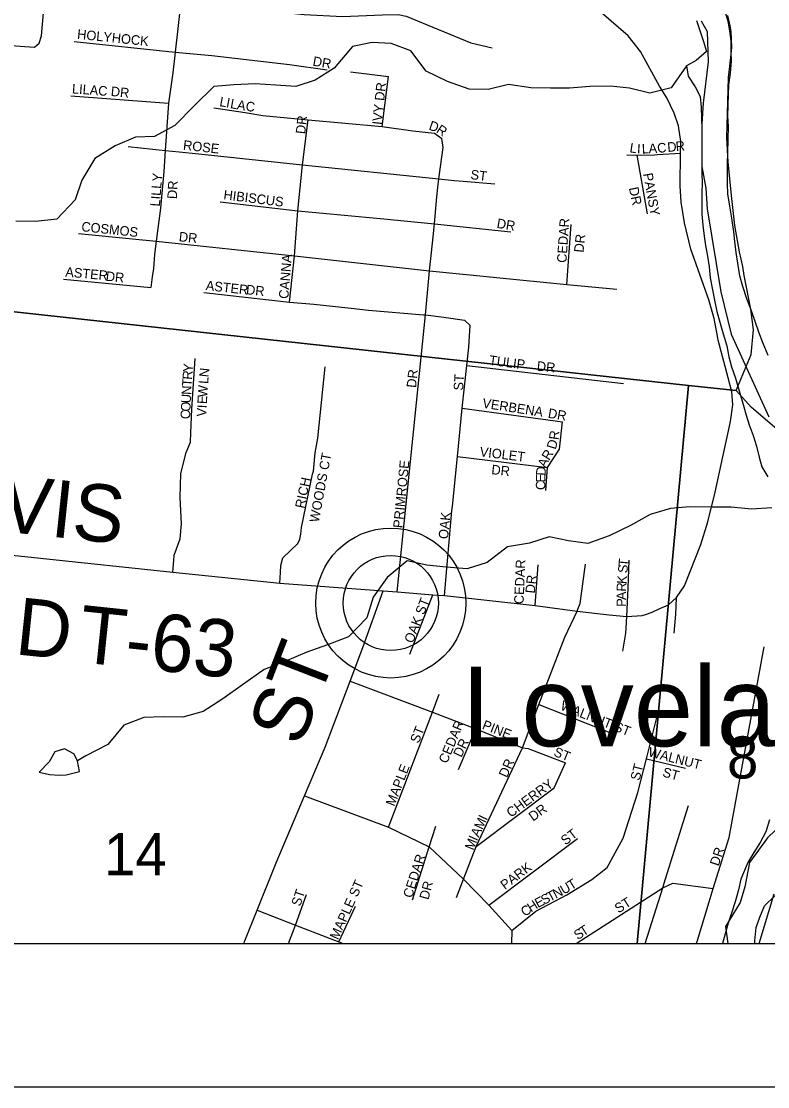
# Model space of a CAD drawing. Extents: x 0 to 34, y -4 to 22.
# Drawn here: x 3.386 to 3.907, y 14 to 14.744 of the extents above; entities that cross this region are included whole.
import ezdxf

# ---------------------------------------------------------------- set-up
doc = ezdxf.new("R2010")
doc.units = 0
for name, color, linetype in [('GM_X_Major_River', 7, 'Continuous'), ('GM_X_Minor_Lake', 7, 'Continuous'), ('GM_X_Minor_River', 7, 'Continuous'), ('GM_X_Section', 7, 'Continuous'), ('GM_X_Section_Text', 7, 'Continuous'), ('GM_X_Township', 7, 'Continuous'), ('GM_X_Township_Road', 7, 'Continuous'), ('GM_X_Township_Road_Text', 7, 'Continuous'), ('GM_X_Township_Subdivision', 7, 'Continuous'), ('GM_X_Township_Subdivision_Text', 7, 'Continuous'), ('GM_X_Unincorporated', 7, 'Continuous'), ('GM_X_Unincorporated_Text', 7, 'Continuous'), ('SH_Data', 7, 'Continuous'), ('SN_P_Text', 7, 'Continuous')]:
    doc.layers.add(name, color=color, linetype=linetype)

msp = doc.modelspace()

# ---------------------------------------------------------------- linework, layer by layer
at = {"layer": 'GM_X_Major_River'}
for points in [[(3.9041, 14.51904), (3.90103, 14.52686), (3.89874, 14.5336), (3.89594, 14.54169), (3.89261, 14.55005), (3.88982, 14.55868), (3.88782, 14.56621), (3.88637, 14.57508), (3.88516, 14.5826), (3.88423, 14.59012), (3.88354, 14.59683), (3.88211, 14.6065), (3.88065, 14.61483), (3.87947, 14.62342), (3.87906, 14.63039), (3.87918, 14.63735), (3.87905, 14.64486), (3.87944, 14.65181), (3.87962, 14.66172), (3.87978, 14.67055), (3.87937, 14.67779), (3.8795, 14.68529), (3.8799, 14.69278), (3.88002, 14.69948), (3.88124, 14.70776), (3.88192, 14.71605), (3.88178, 14.72274), (3.88164, 14.73025), (3.8807, 14.73723), (3.87948, 14.74395), (3.8772, 14.75122)], [(3.85754, 14.74463), (3.86008, 14.73681), (3.86236, 14.7298), (3.86438, 14.7228), (3.85731, 14.71651), (3.85055, 14.71289), (3.85176, 14.70563), (3.85645, 14.69831), (3.86008, 14.69155), (3.86074, 14.68403), (3.86087, 14.676), (3.86127, 14.66876)], [(3.86127, 14.66876), (3.8611, 14.65912), (3.86125, 14.65242), (3.86113, 14.64546), (3.86126, 14.63796), (3.86141, 14.63099), (3.86129, 14.6243), (3.86117, 14.6176), (3.86129, 14.6093), (3.86195, 14.60152), (3.86289, 14.594), (3.86384, 14.58729), (3.86505, 14.58003), (3.86625, 14.57251), (3.86691, 14.56473), (3.86864, 14.5564), (3.87011, 14.54914), (3.87158, 14.54134), (3.87385, 14.5338), (3.87612, 14.52572), (3.87864, 14.51737), (3.88011, 14.50958), (3.88186, 14.50258), (3.88466, 14.49476), (3.88769, 14.48426), (3.88996, 14.47645), (3.89223, 14.4689), (3.89425, 14.46217), (3.89706, 14.45462), (3.89934, 14.44734), (3.90134, 14.43954), (3.90309, 14.43281), (3.90725, 14.42577)], [(3.90743, 14.51067), (3.9041, 14.51904)], [(3.90856, 14.1863), (3.906, 14.17805), (3.90185, 14.17062), (3.89744, 14.16348), (3.8933, 14.15659), (3.88854, 14.14489), (3.8868, 14.13743), (3.88451, 14.12917), (3.88196, 14.12118), (3.87969, 14.11426), (3.87742, 14.1068), (3.87559, 14.1)], [(3.89817, 14.1), (3.8982, 14.10186), (3.89917, 14.11122), (3.90171, 14.1184), (3.90507, 14.12637), (3.91215, 14.1332)]]:
    msp.add_lwpolyline(points, dxfattribs=at)
at = {"layer": 'GM_X_Minor_Lake'}
for points in [[(3.42524, 14.22764), (3.42284, 14.23244), (3.41615, 14.23592), (3.40947, 14.23378), (3.40546, 14.22683), (3.39851, 14.21962), (3.40573, 14.21802), (3.41241, 14.21748), (3.41732, 14.21787)], [(3.41732, 14.21787), (3.42658, 14.22015), (3.42524, 14.22764)]]:
    msp.add_lwpolyline(points, dxfattribs=at)
at = {"layer": 'GM_X_Minor_River'}
for points in [[(3.85055, 14.71289), (3.8397, 14.69743), (3.82499, 14.69369), (3.81081, 14.69717), (3.79743, 14.69877), (3.78299, 14.6985), (3.76881, 14.69717), (3.75543, 14.69717), (3.74179, 14.69744), (3.72627, 14.69984), (3.71209, 14.69637), (3.69872, 14.69663), (3.68373, 14.70198), (3.66875, 14.7092), (3.65805, 14.72336), (3.6444, 14.72844), (3.63102, 14.72925), (3.61738, 14.72631), (3.60454, 14.71134), (3.59117, 14.70278), (3.57779, 14.69851), (3.56388, 14.69931), (3.54944, 14.70038), (3.53446, 14.69958), (3.52055, 14.69851), (3.50691, 14.68514), (3.49327, 14.67124), (3.47909, 14.66349), (3.46571, 14.66296), (3.45153, 14.65708), (3.43736, 14.64826), (3.42827, 14.63302), (3.42372, 14.61939), (3.41088, 14.60576), (3.3959, 14.60415), (3.38226, 14.60442)], [(3.91012, 14.4042), (3.89594, 14.4034), (3.88176, 14.40474), (3.86839, 14.40474), (3.85314, 14.405), (3.83923, 14.40367), (3.82505, 14.39966), (3.81141, 14.39191), (3.79643, 14.38469), (3.78171, 14.37934), (3.76807, 14.38122), (3.75469, 14.38389), (3.74078, 14.37961), (3.72553, 14.37694), (3.71136, 14.36598), (3.69744, 14.3617), (3.68273, 14.36277), (3.66909, 14.36411), (3.65544, 14.36732), (3.64153, 14.35556), (3.63164, 14.34193), (3.62736, 14.32749), (3.61452, 14.31413), (3.5998, 14.30851), (3.58536, 14.30344), (3.57011, 14.29702), (3.55566, 14.29141), (3.54042, 14.28072), (3.52677, 14.27083), (3.51313, 14.26201), (3.49895, 14.258), (3.48531, 14.25827), (3.47166, 14.25773), (3.45775, 14.25239), (3.44652, 14.23902), (3.431, 14.231), (3.42524, 14.22764)]]:
    msp.add_lwpolyline(points, dxfattribs=at)
at = {"layer": 'GM_X_Section'}
for points in [[(3.15948, 14.56518), (3.85199, 14.48967), (3.88525, 14.48607), (3.89561, 14.51119), (3.8973, 14.52848), (3.89545, 14.54292), (3.89086, 14.56648), (3.88992, 14.57263), (3.88746, 14.58307), (3.88436, 14.60127), (3.88208, 14.62024), (3.87966, 14.64562), (3.87866, 14.66271), (3.87978, 14.70481), (3.88139, 14.71865), (3.88207, 14.72583), (3.88176, 14.73677), (3.88104, 14.74078), (3.87931, 14.74802)], [(3.92005, 14.45363), (3.89594, 14.47439), (3.88525, 14.48607), (3.85199, 14.48967), (3.81604, 14.1), (3.90131, 14.1), (3.91178, 14.13465)]]:
    msp.add_lwpolyline(points, dxfattribs=at)
msp.add_lwpolyline([(3.10877, 14.1), (3.81604, 14.1), (3.85199, 14.48967), (3.15948, 14.56518)], close=True, dxfattribs=at)
at = {"layer": 'GM_X_Township'}
for points in [[(3.86069, 14.74433), (3.86489, 14.73695), (3.86564, 14.71564), (3.86222, 14.68684), (3.86111, 14.67268), (3.86114, 14.64255), (3.86389, 14.62743), (3.86495, 14.61294), (3.87457, 14.55512), (3.88172, 14.52545), (3.90792, 14.4677)], [(3.92411, 14.19005), (3.907, 14.17387), (3.89445, 14.15645), (3.89131, 14.1395), (3.88789, 14.12859), (3.8777, 14.11185), (3.87935, 14.1), (7.6703, 14.1)]]:
    msp.add_lwpolyline(points, dxfattribs=at)
at = {"layer": 'GM_X_Township_Road'}
for points in [[(3.87164, 14.52664), (3.86979, 14.53639), (3.8661, 14.54953), (3.85359, 14.58481), (3.84918, 14.60317), (3.84684, 14.61758), (3.84606, 14.62901), (3.84639, 14.6519), (3.84652, 14.66012), (3.84491, 14.67092), (3.84179, 14.67987), (3.83687, 14.69057), (3.83162, 14.6987), (3.81849, 14.72297), (3.80985, 14.73377), (3.78599, 14.75437)], [(3.87657, 14.44302), (3.87861, 14.45268), (3.88131, 14.46448), (3.88275, 14.47618), (3.88212, 14.48527), (3.87969, 14.4949), (3.87267, 14.52118), (3.87164, 14.52664)], [(3.82195, 14.32981), (3.82659, 14.33145), (3.83181, 14.33388), (3.83793, 14.33658), (3.8436, 14.34153), (3.84909, 14.34981), (3.86052, 14.37852), (3.86547, 14.39436), (3.87042, 14.41516), (3.87591, 14.43991), (3.87657, 14.44302)], [(3.30692, 14.37873), (3.49185, 14.35933), (3.56652, 14.35168), (3.63865, 14.34636), (3.6486, 14.34545), (3.67341, 14.34338), (3.68142, 14.343), (3.74478, 14.33595), (3.77415, 14.33212), (3.79644, 14.32947), (3.80877, 14.32839), (3.81948, 14.32893), (3.82195, 14.32981)], [(3.54144, 14.1), (3.54211, 14.1018), (3.5507, 14.12317), (3.56399, 14.15625), (3.58383, 14.20303), (3.59826, 14.23707), (3.61564, 14.28317), (3.62447, 14.30657), (3.63865, 14.34636)]]:
    msp.add_lwpolyline(points, dxfattribs=at)
at = {"layer": 'GM_X_Township_Subdivision'}
for points in [[(3.50538, 14.82838), (3.50071, 14.79605), (3.4987, 14.77523), (3.49739, 14.75759), (3.49345, 14.72231), (3.49192, 14.70786), (3.48874, 14.68683), (3.48646, 14.65384), (3.48549, 14.63897), (3.48331, 14.61342), (3.48031, 14.59038), (3.47958, 14.58508)], [(3.3952, 14.72586), (3.39849, 14.72871), (3.40013, 14.73379), (3.40163, 14.74987), (3.40335, 14.76873), (3.4042, 14.77779), (3.40519, 14.78066), (3.40663, 14.78614), (3.40674, 14.79186), (3.40534, 14.79432), (3.40251, 14.79513), (3.39944, 14.7945), (3.39785, 14.79292), (3.39722, 14.79027), (3.39817, 14.78752), (3.40029, 14.78582), (3.40229, 14.7835), (3.40431, 14.78117)], [(3.42469, 14.76541), (3.49739, 14.75759), (3.58357, 14.74866), (3.61027, 14.74728), (3.63835, 14.74839), (3.64928, 14.74866), (3.65481, 14.74756), (3.69991, 14.72888), (3.71471, 14.72543)], [(3.18884, 14.68116), (3.20908, 14.6793), (3.22743, 14.67658), (3.23539, 14.67574), (3.24391, 14.6763), (3.25324, 14.67805), (3.26511, 14.68283), (3.27157, 14.68674), (3.28623, 14.6971), (3.30592, 14.71168), (3.31696, 14.71943), (3.325, 14.72533), (3.33507, 14.72918), (3.34215, 14.73036), (3.35051, 14.7294), (3.35963, 14.72863), (3.37205, 14.72747), (3.3952, 14.72586)], [(3.42289, 14.72985), (3.49345, 14.72231), (3.51904, 14.72017), (3.57327, 14.71387), (3.59955, 14.71014)], [(3.6159, 14.70871), (3.64248, 14.7055)], [(3.63798, 14.67055), (3.64248, 14.7055)], [(3.42068, 14.69181), (3.48874, 14.68683)], [(3.5204, 14.68352), (3.54233, 14.68017)], [(3.54233, 14.68017), (3.5548, 14.67827), (3.58642, 14.67527)], [(3.57321, 14.54787), (3.57677, 14.5803), (3.57907, 14.61168), (3.58246, 14.64365), (3.58642, 14.67527)], [(3.58642, 14.67527), (3.63798, 14.67055), (3.65931, 14.66755), (3.67463, 14.66573), (3.67956, 14.66219)], [(3.46073, 14.6566), (3.48646, 14.65384), (3.49627, 14.65283)], [(3.67686, 14.62789), (3.67753, 14.6339), (3.68053, 14.65576), (3.67956, 14.66219)], [(3.49627, 14.65283), (3.50998, 14.65142), (3.58246, 14.64365), (3.67753, 14.6339), (3.68827, 14.63288)], [(3.80887, 14.65077), (3.81611, 14.65042), (3.82823, 14.6508)], [(3.82316, 14.60953), (3.81611, 14.65042)], [(3.82823, 14.6508), (3.83028, 14.65087), (3.84639, 14.6519)], [(3.67362, 14.59343), (3.67463, 14.6026), (3.67613, 14.62146), (3.67686, 14.62789)], [(3.68827, 14.63288), (3.69457, 14.63229), (3.71676, 14.63047)], [(3.5249, 14.61793), (3.57907, 14.61168), (3.63926, 14.60603), (3.66991, 14.60306)], [(3.66991, 14.60306), (3.67463, 14.6026), (3.72791, 14.59702)], [(3.76692, 14.56015), (3.76992, 14.60217)], [(3.42596, 14.59585), (3.48031, 14.59038), (3.57677, 14.5803), (3.6711, 14.5698), (3.76692, 14.56015), (3.80187, 14.55694)], [(3.6486, 14.34545), (3.6683, 14.53888), (3.6711, 14.5698), (3.67313, 14.58909), (3.67362, 14.59343)], [(3.47958, 14.58508), (3.47902, 14.58105), (3.47827, 14.5713), (3.47752, 14.56562), (3.47656, 14.55801)], [(3.41556, 14.5638), (3.47656, 14.55801)], [(3.51349, 14.55453), (3.57321, 14.54787)], [(3.57321, 14.54787), (3.59031, 14.54642), (3.61641, 14.54365)], [(3.61641, 14.54365), (3.62858, 14.54236), (3.66683, 14.53901)], [(3.66683, 14.53901), (3.6683, 14.53888), (3.68105, 14.53743), (3.6955, 14.53516)], [(3.68706, 14.40542), (3.69072, 14.44005), (3.69383, 14.47391), (3.69706, 14.5035), (3.69848, 14.51642), (3.69951, 14.53154), (3.6955, 14.53516)], [(3.49185, 14.35933), (3.4925, 14.36748), (3.49289, 14.37119), (3.49691, 14.38251), (3.49788, 14.3931), (3.49691, 14.41139), (3.49753, 14.42809), (3.50124, 14.44294), (3.50413, 14.45009), (3.5044, 14.45655), (3.50523, 14.47305), (3.50619, 14.49092), (3.5075, 14.50859)], [(3.56652, 14.35168), (3.56703, 14.35915), (3.56736, 14.36405), (3.56871, 14.3692), (3.57921, 14.37938), (3.58056, 14.38234), (3.58127, 14.38582), (3.58178, 14.39046), (3.5894, 14.42777), (3.58999, 14.42993), (3.59113, 14.44259), (3.59307, 14.45295), (3.59824, 14.50276)], [(3.69706, 14.5035), (3.80657, 14.49112)], [(3.69383, 14.47391), (3.76391, 14.46432)], [(3.75237, 14.41627), (3.7534, 14.43242), (3.76173, 14.44518), (3.76391, 14.46432)], [(3.69072, 14.44005), (3.7534, 14.43242)], [(3.68142, 14.343), (3.68672, 14.40218), (3.68706, 14.40542)], [(3.80985, 14.34805), (3.80985, 14.3481), (3.81057, 14.36772)], [(3.74478, 14.33595), (3.74694, 14.3643)], [(3.77471, 14.33353), (3.77619, 14.3373), (3.78007, 14.36499)], [(3.80839, 14.32023), (3.80877, 14.32839), (3.80985, 14.34805)], [(3.65739, 14.30203), (3.67341, 14.34338)], [(3.84331, 14.33533), (3.8436, 14.34153)], [(3.6948, 14.14488), (3.70374, 14.16769), (3.73596, 14.23659), (3.74748, 14.26692), (3.76548, 14.31399), (3.77415, 14.33212), (3.77471, 14.33353)], [(3.842, 14.31678), (3.84306, 14.33001), (3.84331, 14.33533)], [(3.80607, 14.30409), (3.80823, 14.31669), (3.80839, 14.32023)], [(3.86626, 14.12899), (3.86631, 14.12915), (3.86918, 14.13837), (3.88027, 14.17394), (3.90468, 14.30711)], [(3.61564, 14.28317), (3.67304, 14.26143), (3.70348, 14.24991), (3.73596, 14.23659), (3.73993, 14.2361), (3.741, 14.2357)], [(3.64243, 14.18123), (3.67304, 14.26143), (3.6779, 14.27418)], [(3.74748, 14.26692), (3.79815, 14.24694)], [(3.72848, 14.10898), (3.7454, 14.12257), (3.76704, 14.13404), (3.78444, 14.14465), (3.79515, 14.15306), (3.80622, 14.17362), (3.81655, 14.20541), (3.82249, 14.22891), (3.82979, 14.25785)], [(3.69133, 14.22151), (3.70348, 14.24991)], [(3.741, 14.2357), (3.7661, 14.22619)], [(3.70374, 14.16769), (3.75812, 14.20858), (3.7661, 14.22619)], [(3.82249, 14.22891), (3.84969, 14.22252)], [(3.58383, 14.20303), (3.64243, 14.18123), (3.67089, 14.1674), (3.6948, 14.14488), (3.7124, 14.12672), (3.72848, 14.10898), (3.72822, 14.1)], [(3.83461, 14.14128), (3.83463, 14.14136), (3.85193, 14.19647)], [(3.65917, 14.13038), (3.67089, 14.1674), (3.6755, 14.18193)], [(3.7124, 14.12672), (3.77433, 14.17323)], [(3.68984, 14.1322), (3.6948, 14.14488)], [(3.77343, 14.1), (3.83387, 14.13894), (3.84095, 14.14212), (3.84103, 14.14211)], [(3.82165, 14.1), (3.83387, 14.13894), (3.83461, 14.14128)], [(3.84103, 14.14211), (3.86918, 14.13837)], [(3.57272, 14.1), (3.57739, 14.11286), (3.58513, 14.13412)], [(3.85732, 14.1), (3.85783, 14.10135), (3.86626, 14.12899)], [(3.5507, 14.12317), (3.57739, 14.11286), (3.60765, 14.10117), (3.61069, 14.1)], [(3.60765, 14.10117), (3.61928, 14.12605)]]:
    msp.add_lwpolyline(points, dxfattribs=at)
at = {"layer": 'GM_X_Unincorporated'}
for radius in [0.05238, 0.0332]:
    msp.add_circle((3.64404, 14.33775), radius, dxfattribs=at)
at = {"layer": 'SH_Data'}
for p, q in [((2.1, 14.1), (8.9, 14.1)), ((2, 14), (9, 14))]:
    msp.add_line(p, q, dxfattribs=at)
at = {"layer": 'SN_P_Text'}
msp.add_lwpolyline([(8.9, 14.1), (8.9, 20.9), (2.1, 20.9), (2.1, 14.1)], close=True, dxfattribs=at)

# ---------------------------------------------------------------- texts
at = {"layer": 'GM_X_Section_Text'}
for s, height, p in [('8', 0.02944, (3.87878, 14.21519)), ('14', 0.029444, (3.44377, 14.14765))]:
    msp.add_text(s, height=height, rotation=0.00001, dxfattribs=at).set_placement(p)
at = {"layer": 'GM_X_Township_Road_Text'}
for s, rotation, p in [('DAVIS', 353.93703, (3.29632, 14.39585)), ('RD', 354.04225, (3.34248, 14.30604)), ('T-63', 354.00977, (3.42485, 14.2966)), ('ST', 68.93202, (3.581, 14.23643))]:
    msp.add_text(s, height=0.04, rotation=rotation, dxfattribs=at).set_placement(p)
at = {"layer": 'GM_X_Township_Subdivision_Text'}
for s, height, rotation, p in [('HOLYHOCK', 0.006667, 354.14157, (3.42483, 14.73178)), ('DR', 0.006667, 350.53177, (3.58918, 14.71299)), ('IVY DR', 0.006667, 83.93096, (3.63759, 14.67141)), ('LILAC', 0.006667, 355.81741, (3.42127, 14.69365)), ('DR', 0.006667, 353.98321, (3.4483, 14.69188)), ('L', 0.00667, 349.42397, (3.52408, 14.68483)), ('I', 0.00667, 349.42924, (3.5287, 14.68397)), ('L', 0.00667, 349.41896, (3.53158, 14.68343)), ('A', 0.00667, 349.87549, (3.53625, 14.68256)), ('C', 0.00667, 353.24852, (3.54245, 14.68146)), ('DR', 0.006667, 83.66379, (3.58421, 14.66496)), ('D', 0.00667, 341.12969, (3.67009, 14.66843)), ('R', 0.00667, 326.35709, (3.67524, 14.66673)), ('ROSE', 0.006667, 353.65714, (3.49876, 14.65434)), ('L', 0.00667, 351.0856, (3.81046, 14.65255)), ('I', 0.00667, 356.57117, (3.81579, 14.65175)), ('L', 0.00667, 2.36536, (3.81945, 14.65156)), ('A', 0.00667, 2.90186, (3.82421, 14.65176)), ('C', 0.00667, 4.84004, (3.83031, 14.65207)), ('D', 0.00667, 5.36843, (3.8374, 14.65269)), ('R', 0.00667, 5.35054, (3.84324, 14.65323)), ('LILLY', 0.006667, 85.71328, (3.48279, 14.61446)), ('ST', 0.006667, 352.88003, (3.69942, 14.6338)), ('PANSY', 0.006667, 280.07945, (3.82018, 14.63747)), ('DR', 0.006667, 86.98901, (3.49462, 14.61971)), ('HIBISCUS', 0.006667, 352.76357, (3.52694, 14.61972)), ('DR', 0.006667, 281.89272, (3.81024, 14.62754)), ('COSMOS', 0.006667, 353.9904, (3.42777, 14.59743)), ('DR', 0.006667, 350.54359, (3.71766, 14.59977)), ('CEDAR', 0.006667, 86.26602, (3.76665, 14.57514)), ('DR', 0.006667, 353.99339, (3.49582, 14.59039)), ('DR', 0.006667, 83.9832, (3.77852, 14.58222)), ('CANNA', 0.006667, 85.33566, (3.57247, 14.54994)), ('ASTER', 0.006667, 354.80333, (3.4166, 14.56575)), ('DR', 0.006667, 353.99459, (3.44478, 14.56282)), ('ASTER', 0.006667, 353.52027, (3.5146, 14.55636)), ('DR', 0.006667, 353.98321, (3.54275, 14.55343)), ('TULIP', 0.006667, 352.50221, (3.71233, 14.50415)), ('R', 0.00667, 85.30695, (3.50519, 14.49349)), ('Y', 0.00667, 85.22909, (3.50562, 14.49874)), ('N', 0.00667, 84.17632, (3.51684, 14.4952)), ('DR', 0.006667, 83.99458, (3.66164, 14.48778)), ('DR', 0.006667, 353.98321, (3.74574, 14.50005)), ('T', 0.00667, 86.30949, (3.50489, 14.48883)), ('L', 0.00667, 85.24089, (3.51645, 14.49056)), ('ST', 0.006667, 86.42621, (3.69449, 14.48597)), ('N', 0.00667, 87.33571, (3.50462, 14.483)), ('W', 0.00667, 86.44988, (3.51585, 14.48123)), ('O', 0.00667, 87.33293, (3.50407, 14.47128)), ('U', 0.00667, 87.3111, (3.50434, 14.47714)), ('E', 0.00667, 86.99295, (3.51561, 14.47656)), ('VERBENA', 0.006667, 351.25561, (3.70767, 14.47422)), ('C', 0.00667, 87.32797, (3.50382, 14.466)), ('V', 0.00667, 87.06992, (3.51516, 14.46777)), ('I', 0.00667, 87.06988, (3.51546, 14.47363)), ('DR', 0.006667, 350.5298, (3.75344, 14.46718)), ('R', 0.00667, 82.6744, (3.76104, 14.4514)), ('D', 0.00667, 72.94705, (3.75906, 14.44459)), ('WOODS CT', 0.006667, 79.6277, (3.59373, 14.39368)), ('VIOLET', 0.006667, 353.15654, (3.70587, 14.4402)), ('R', 0.00667, 58.18251, (3.75456, 14.43689)), ('PRIMROSE', 0.006667, 84.20724, (3.65225, 14.3898)), ('DR', 0.006667, 353.98321, (3.71404, 14.42775)), ('D', 0.00667, 86.785, (3.75204, 14.42654)), ('A', 0.00667, 65.26302, (3.75221, 14.43176)), ('RICH', 0.006667, 78.02425, (3.58363, 14.40343)), ('E', 0.00667, 89.64432, (3.75202, 14.42193)), ('C', 0.00667, 89.63567, (3.75198, 14.41665)), ('OAK', 0.006667, 84.29228, (3.68394, 14.38217)), ('CEDAR', 0.006667, 87.56473, (3.73673, 14.33686)), ('T', 0.00667, 85.10246, (3.80959, 14.36308)), ('S', 0.00667, 85.10246, (3.80919, 14.3584)), ('DR', 0.006667, 83.99458, (3.74451, 14.34422)), ('R', 0.00667, 87.40073, (3.80831, 14.3456)), ('K', 0.00667, 85.22909, (3.80855, 14.35081)), ('A', 0.00667, 89.92532, (3.80831, 14.33981)), ('OAK ST', 0.006667, 68.6283, (3.65938, 14.30917)), ('P', 0.00667, 89.91802, (3.8083, 14.33511)), ('WALNUT ST', 0.006667, 338.59742, (3.76191, 14.26354)), ('CEDAR', 0.006667, 67.28347, (3.6833, 14.22522)), ('PINE', 0.006667, 338.55613, (3.70735, 14.25004)), ('ST', 0.006667, 68.19607, (3.66348, 14.23937)), ('DR', 0.006667, 64.8032, (3.69331, 14.22949)), ('ST', 0.006667, 338.19608, (3.75722, 14.23127)), ('WALNUT', 0.006667, 345.73213, (3.82336, 14.23074)), ('MAPLE', 0.006667, 68.87665, (3.64647, 14.19536)), ('DR', 0.006667, 66.04089, (3.72518, 14.21533)), ('ST', 0.006667, 75.97018, (3.81772, 14.2134)), ('ST', 0.006667, 345.06224, (3.83332, 14.21672)), ('CHERRY', 0.006667, 36.25573, (3.72786, 14.1877)), ('DR', 0.006667, 36.24941, (3.74336, 14.18501)), ('M', 0.00667, 64.80372, (3.70792, 14.17909)), ('I', 0.00667, 64.80352, (3.71092, 14.18546)), ('ST', 0.006667, 37.57346, (3.76596, 14.16832)), ('M', 0.00667, 68.20534, (3.70164, 14.16467)), ('I', 0.00667, 65.5271, (3.70422, 14.17113)), ('A', 0.00667, 64.80352, (3.70542, 14.17378)), ('DR', 0.006667, 71.5614, (3.8729, 14.15365)), ('CEDAR', 0.006667, 72.35089, (3.65876, 14.13134)), ('PARK', 0.006667, 37.18454, (3.72373, 14.13724)), ('MAPLE ST', 0.006667, 65.7724, (3.60719, 14.10214)), ('DR', 0.006667, 75.25417, (3.6703, 14.13015)), ('U', 0.00667, 30.09549, (3.76475, 14.13401)), ('T', 0.00667, 31.97879, (3.77003, 14.13707)), ('ST', 0.006667, 71.57378, (3.58074, 14.12549)), ('T', 0.00667, 27.22919, (3.75504, 14.129)), ('N', 0.00667, 27.23943, (3.75921, 14.13115)), ('H', 0.00667, 33.18695, (3.74196, 14.12155)), ('E', 0.00667, 27.70128, (3.74672, 14.12468)), ('S', 0.00667, 27.23693, (3.75087, 14.12686)), ('ST', 0.006667, 32.73207, (3.80301, 14.12087)), ('C', 0.00667, 36.6416, (3.73781, 14.11846)), ('T', 0.00667, 33.07059, (3.77848, 14.1048)), ('S', 0.00667, 33.07059, (3.77455, 14.10224))]:
    msp.add_text(s, height=height, rotation=rotation, dxfattribs=at).set_placement(p)
at = {"layer": 'GM_X_Unincorporated_Text'}
msp.add_text('Loveland Park', height=0.0555556, rotation=0.00001, dxfattribs=at).set_placement((3.69398, 14.2377))

doc.saveas('drawing.dxf')
